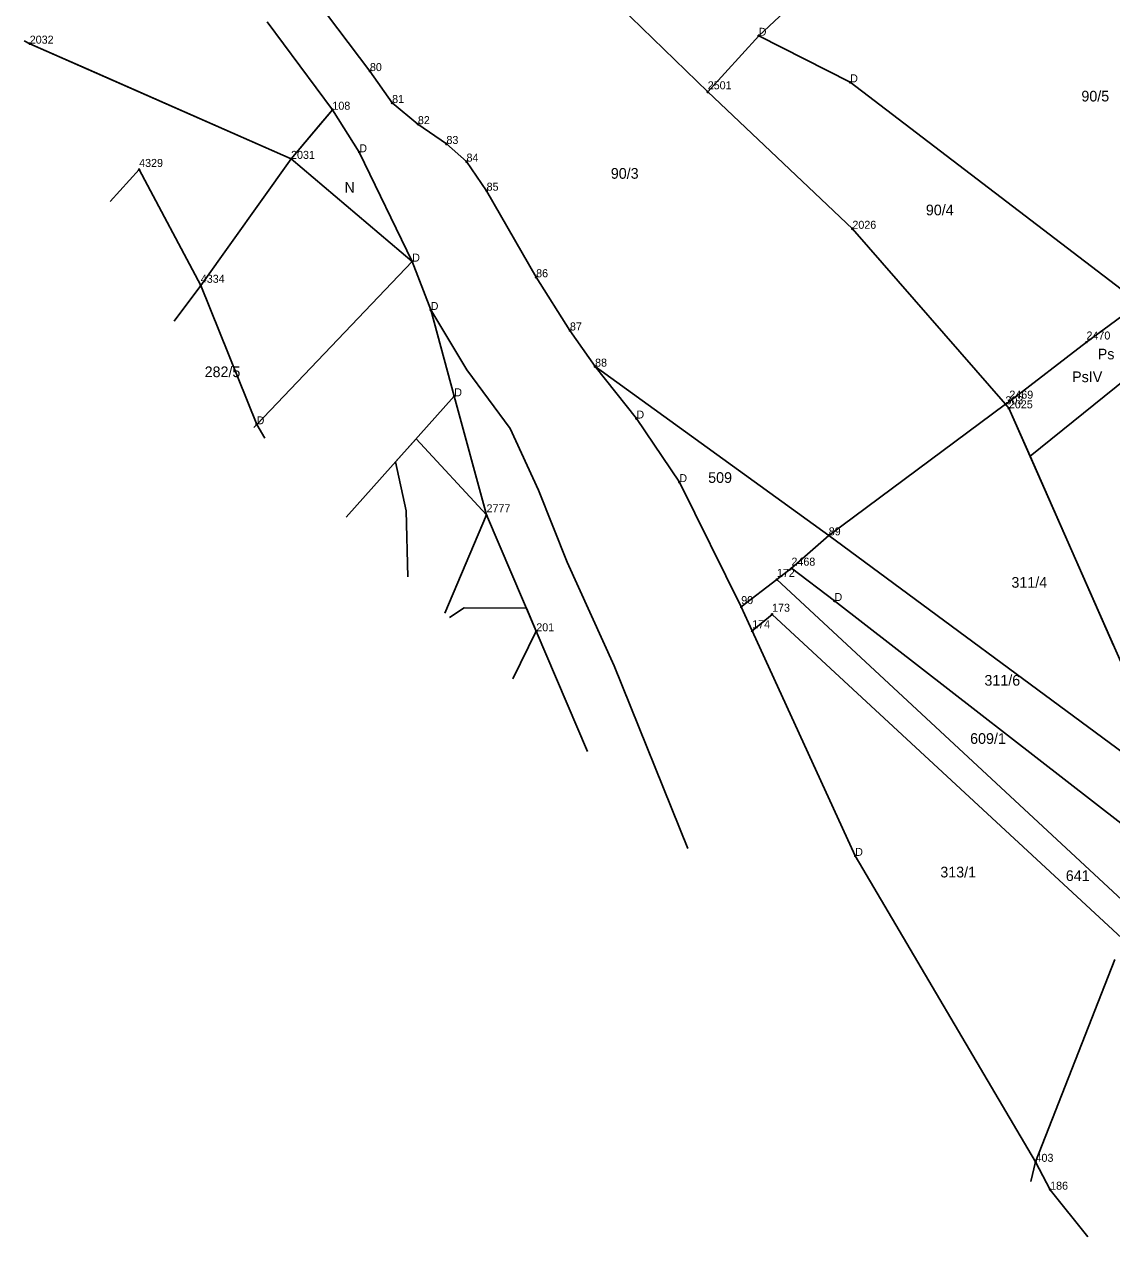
# Model space of a CAD drawing. Extents: x 7467189 to 7469366, y 5491487 to 5492734.
# Drawn here: x 7467502.5 to 7467655.3, y 5491844.1 to 5492014.5 of the extents above; entities that cross this region are included whole.
import ezdxf

# ---------------------------------------------------------------- set-up
doc = ezdxf.new("R2010")
doc.units = 0
for name, color, linetype in [('203-punkt graniczny', 7, 'Continuous'), ('203-punkt graniczny-Atr103', 7, 'Continuous'), ('209-oznaczenie konturu klasyfikacyjnego', 7, 'Continuous'), ('210-oznaczenie konturu użytku gruntowego', 7, 'Continuous'), ('211-numer działki ewidencyjnej', 7, 'Continuous'), ('217-kontur klasyfikacyjny', 7, 'Continuous'), ('218-kontur użytku gruntowego', 7, 'Continuous'), ('219-działka ewidencyjna', 7, 'Continuous')]:
    doc.layers.add(name, color=color, linetype=linetype)

# ---------------------------------------------------------------- blocks, each defined once
blk = doc.blocks.new('203')
blk.add_circle((0, 0), 0.09)

msp = doc.modelspace()

# ---------------------------------------------------------------- linework, layer by layer
at = {"layer": '217-kontur klasyfikacyjny'}
for points in [[(7467581.56, 5492021.52), (7467598.57, 5492004.96)], [(7467503.32, 5492011.74), (7467502.55, 5492012.14)], [(7467511.25, 5492008.24), (7467503.32, 5492011.74)], [(7467540.03, 5491995.55), (7467511.25, 5492008.24)], [(7467598.57, 5492004.96), (7467618.89, 5491985.73)], [(7467527.35, 5491977.76), (7467540.03, 5491995.55)], [(7467514.64, 5491989.54), (7467518.69, 5491994.05)], [(7467518.69, 5491994.05), (7467527.35, 5491977.76)], [(7467618.89, 5491985.73), (7467640.39, 5491961.07)], [(7467535.2, 5491958.25), (7467527.35, 5491977.76)], [(7467659.21, 5491975.28), (7467651.78, 5491969.8)], [(7467643.85, 5491953.77), (7467666.33, 5491971.9)], [(7467651.78, 5491969.8), (7467640.94, 5491961.48)], [(7467640.94, 5491961.48), (7467640.39, 5491961.07)], [(7467640.39, 5491961.07), (7467640.88, 5491960.5)], [(7467640.88, 5491960.5), (7467643.85, 5491953.77)], [(7467536.33, 5491956.3), (7467535.2, 5491958.25)], [(7467643.85, 5491953.77), (7467655.58, 5491927.15)], [(7467564.33, 5491932.48), (7467562.29, 5491931.11)], [(7467573.09, 5491932.44), (7467564.33, 5491932.48)], [(7467574.48, 5491929.17), (7467573.09, 5491932.44)], [(7467581.67, 5491912.3), (7467574.48, 5491929.17)], [(7467655.78, 5491883.07), (7467644.62, 5491854.62)], [(7467644.62, 5491854.62), (7467646.67, 5491850.7)], [(7467646.67, 5491850.7), (7467651.97, 5491844.09)]]:
    msp.add_lwpolyline(points, dxfattribs=at)
at = {"layer": '218-kontur użytku gruntowego'}
for points in [[(7467581.56, 5492021.52), (7467598.57, 5492004.96)], [(7467503.32, 5492011.74), (7467502.55, 5492012.14)], [(7467511.25, 5492008.24), (7467503.32, 5492011.74)], [(7467540.03, 5491995.55), (7467511.25, 5492008.24)], [(7467598.57, 5492004.96), (7467618.89, 5491985.73)], [(7467545.84, 5492002.46), (7467544.2, 5492000.51)], [(7467549.62, 5491996.48), (7467545.84, 5492002.46)], [(7467544.2, 5492000.51), (7467540.03, 5491995.55)], [(7467557.05, 5491981.12), (7467549.62, 5491996.48)], [(7467527.35, 5491977.76), (7467540.03, 5491995.55)], [(7467540.03, 5491995.55), (7467557.05, 5491981.12)], [(7467514.64, 5491989.54), (7467518.69, 5491994.05)], [(7467518.69, 5491994.05), (7467527.35, 5491977.76)], [(7467618.89, 5491985.73), (7467640.39, 5491961.07)], [(7467559.65, 5491974.32), (7467557.05, 5491981.12)], [(7467535.2, 5491958.25), (7467527.35, 5491977.76)], [(7467562.96, 5491962.19), (7467559.65, 5491974.32)], [(7467564.73, 5491965.9), (7467559.65, 5491974.32)], [(7467659.21, 5491975.28), (7467651.78, 5491969.8)], [(7467643.85, 5491953.77), (7467666.33, 5491971.9)], [(7467651.78, 5491969.8), (7467640.94, 5491961.48)], [(7467570.8, 5491957.67), (7467564.73, 5491965.9)], [(7467567.49, 5491945.51), (7467562.96, 5491962.19)], [(7467640.94, 5491961.48), (7467640.39, 5491961.07)], [(7467640.39, 5491961.07), (7467640.88, 5491960.5)], [(7467640.88, 5491960.5), (7467643.85, 5491953.77)], [(7467536.33, 5491956.3), (7467535.2, 5491958.25)], [(7467574.81, 5491948.99), (7467570.8, 5491957.67)], [(7467554.71, 5491952.96), (7467557.6, 5491956.19)], [(7467557.6, 5491956.19), (7467567.49, 5491945.51)], [(7467643.85, 5491953.77), (7467655.58, 5491927.15)], [(7467556.19, 5491946.09), (7467554.71, 5491952.96)], [(7467578.83, 5491938.89), (7467574.81, 5491948.99)], [(7467556.42, 5491936.81), (7467556.19, 5491946.09)], [(7467585.41, 5491924.33), (7467578.83, 5491938.89)], [(7467603.27, 5491932.61), (7467608.28, 5491936.44)], [(7467608.28, 5491936.44), (7467658.12, 5491890.18)], [(7467564.33, 5491932.48), (7467562.29, 5491931.11)], [(7467573.09, 5491932.44), (7467564.33, 5491932.48)], [(7467574.48, 5491929.17), (7467573.09, 5491932.44)], [(7467604.82, 5491929.22), (7467603.27, 5491932.61)], [(7467607.61, 5491931.54), (7467604.82, 5491929.22)], [(7467656.76, 5491886.05), (7467607.61, 5491931.54)], [(7467581.67, 5491912.3), (7467574.48, 5491929.17)], [(7467595.76, 5491898.63), (7467585.41, 5491924.33)], [(7467655.78, 5491883.07), (7467644.62, 5491854.62)], [(7467644.62, 5491854.62), (7467643.96, 5491851.86)], [(7467646.67, 5491850.7), (7467644.62, 5491854.62)], [(7467651.97, 5491844.09), (7467646.67, 5491850.7)]]:
    msp.add_lwpolyline(points, dxfattribs=at)
at = {"layer": '219-działka ewidencyjna'}
for points in [[(7467605.73, 5492012.85), (7467635.43, 5492040.66)], [(7467581.56, 5492021.52), (7467598.57, 5492004.96)], [(7467543.56, 5492017.84), (7467551.11, 5492007.89)], [(7467536.67, 5492014.81), (7467545.84, 5492002.46)], [(7467502.55, 5492012.14), (7467503.32, 5492011.74)], [(7467503.32, 5492011.74), (7467540.03, 5491995.55)], [(7467605.73, 5492012.85), (7467598.57, 5492004.96)], [(7467605.73, 5492012.85), (7467618.58, 5492006.31)], [(7467551.11, 5492007.89), (7467554.23, 5492003.41)], [(7467618.58, 5492006.31), (7467659.21, 5491975.28)], [(7467618.89, 5491985.73), (7467598.57, 5492004.96)], [(7467554.23, 5492003.41), (7467557.85, 5492000.43)], [(7467540.03, 5491995.55), (7467545.84, 5492002.46)], [(7467545.84, 5492002.46), (7467549.62, 5491996.48)], [(7467557.85, 5492000.43), (7467561.86, 5491997.65)], [(7467549.62, 5491996.48), (7467557.05, 5491981.12)], [(7467561.86, 5491997.65), (7467564.68, 5491995.17)], [(7467540.03, 5491995.55), (7467527.35, 5491977.76)], [(7467564.68, 5491995.17), (7467567.5, 5491991.08)], [(7467514.64, 5491989.54), (7467518.69, 5491994.05)], [(7467518.69, 5491994.05), (7467527.35, 5491977.76)], [(7467567.5, 5491991.08), (7467574.46, 5491978.92)], [(7467618.89, 5491985.73), (7467640.39, 5491961.07)], [(7467535.2, 5491958.25), (7467557.05, 5491981.12)], [(7467557.05, 5491981.12), (7467559.65, 5491974.32)], [(7467523.62, 5491972.74), (7467527.35, 5491977.76)], [(7467574.46, 5491978.92), (7467579.21, 5491971.44)], [(7467559.65, 5491974.32), (7467562.96, 5491962.19)], [(7467659.21, 5491975.28), (7467651.78, 5491969.8)], [(7467579.21, 5491971.44), (7467582.74, 5491966.36)], [(7467640.94, 5491961.48), (7467651.78, 5491969.8)], [(7467582.74, 5491966.36), (7467588.55, 5491959.07)], [(7467582.74, 5491966.36), (7467615.57, 5491942.65)], [(7467547.77, 5491945.2), (7467562.96, 5491962.19)], [(7467562.96, 5491962.19), (7467567.49, 5491945.51)], [(7467615.57, 5491942.65), (7467640.39, 5491961.07)], [(7467640.39, 5491961.07), (7467640.94, 5491961.48)], [(7467640.39, 5491961.07), (7467640.88, 5491960.5)], [(7467640.88, 5491960.5), (7467658.36, 5491920.84)], [(7467588.55, 5491959.07), (7467594.58, 5491950.13)], [(7467534.78, 5491957.81), (7467535.2, 5491958.25)], [(7467594.58, 5491950.13), (7467603.27, 5491932.61)], [(7467561.65, 5491931.73), (7467567.49, 5491945.51)], [(7467574.48, 5491929.17), (7467567.49, 5491945.51)], [(7467615.57, 5491942.65), (7467610.33, 5491938.02)], [(7467615.57, 5491942.65), (7467659.1, 5491910.5)], [(7467603.27, 5491932.61), (7467608.28, 5491936.44)], [(7467608.28, 5491936.44), (7467610.33, 5491938.02)], [(7467608.28, 5491936.44), (7467658.12, 5491890.18)], [(7467616.38, 5491933.43), (7467610.33, 5491938.02)], [(7467616.38, 5491933.43), (7467660.98, 5491898.77)], [(7467603.27, 5491932.61), (7467604.82, 5491929.22)], [(7467604.82, 5491929.22), (7467607.61, 5491931.54)], [(7467607.61, 5491931.54), (7467656.76, 5491886.05)], [(7467571.18, 5491922.49), (7467574.48, 5491929.17)], [(7467574.48, 5491929.17), (7467581.67, 5491912.3)], [(7467619.28, 5491897.61), (7467604.82, 5491929.22)], [(7467619.28, 5491897.61), (7467644.62, 5491854.62)], [(7467644.62, 5491854.62), (7467655.78, 5491883.07)], [(7467644.62, 5491854.62), (7467646.67, 5491850.7)], [(7467646.67, 5491850.7), (7467651.97, 5491844.09)]]:
    msp.add_lwpolyline(points, dxfattribs=at)

# ---------------------------------------------------------------- block references
at = {"layer": '203-punkt graniczny'}
for p in [(7467503.32, 5492011.74), (7467605.73, 5492012.85), (7467551.11, 5492007.89), (7467618.58, 5492006.31), (7467598.57, 5492004.96), (7467554.23, 5492003.41), (7467545.84, 5492002.46), (7467557.85, 5492000.43), (7467549.62, 5491996.48), (7467561.86, 5491997.65), (7467540.03, 5491995.55), (7467564.68, 5491995.17), (7467518.69, 5491994.05), (7467567.5, 5491991.08), (7467618.89, 5491985.73), (7467557.05, 5491981.12), (7467527.35, 5491977.76), (7467574.46, 5491978.92), (7467559.65, 5491974.32), (7467579.21, 5491971.44), (7467651.78, 5491969.8), (7467582.74, 5491966.36), (7467562.96, 5491962.19), (7467640.39, 5491961.07), (7467640.88, 5491960.5), (7467640.94, 5491961.48), (7467588.55, 5491959.07), (7467535.2, 5491958.25), (7467594.58, 5491950.13), (7467567.49, 5491945.51), (7467615.57, 5491942.65), (7467608.28, 5491936.44), (7467610.33, 5491938.02), (7467616.38, 5491933.43), (7467603.27, 5491932.61), (7467607.61, 5491931.54), (7467574.48, 5491929.17), (7467604.82, 5491929.22), (7467619.28, 5491897.61), (7467644.62, 5491854.62), (7467646.67, 5491850.7)]:
    msp.add_blockref('203', p, dxfattribs=at)

# ---------------------------------------------------------------- texts
at = {"layer": '203-punkt graniczny-Atr103'}
for s, height, p in [('D', 1.12, (7467605.73, 5492012.85)), ('2032', 1.125, (7467503.32, 5492011.74)), ('80', 1.125, (7467551.11, 5492007.89)), ('2501', 1.125, (7467598.57, 5492005.33)), ('D', 1.12, (7467618.58, 5492006.31)), ('108', 1.125, (7467545.84, 5492002.46)), ('81', 1.125, (7467554.23, 5492003.41)), ('82', 1.125, (7467557.85, 5492000.43)), ('83', 1.125, (7467561.86, 5491997.65)), ('2031', 1.125, (7467540.03, 5491995.55)), ('D', 1.12, (7467549.62, 5491996.48)), ('84', 1.125, (7467564.68, 5491995.17)), ('4329', 1.125, (7467518.69, 5491994.42)), ('85', 1.125, (7467567.5, 5491991.08)), ('2026', 1.125, (7467618.89, 5491985.73)), ('D', 1.12, (7467557.05, 5491981.12)), ('4334', 1.125, (7467527.35, 5491978.14)), ('86', 1.125, (7467574.46, 5491978.92)), ('D', 1.12, (7467559.65, 5491974.32)), ('87', 1.125, (7467579.21, 5491971.44)), ('2470', 1.125, (7467651.78, 5491970.17)), ('88', 1.125, (7467582.74, 5491966.36)), ('D', 1.12, (7467562.96, 5491962.19)), ('303', 1.125, (7467640.39, 5491961.07)), ('2469', 1.125, (7467640.94, 5491961.86)), ('2025', 1.125, (7467640.88, 5491960.5)), ('D', 1.12, (7467535.2, 5491958.25)), ('D', 1.12, (7467588.55, 5491959.07)), ('D', 1.12, (7467594.58, 5491950.13)), ('2777', 1.125, (7467567.49, 5491945.89)), ('89', 1.125, (7467615.57, 5491942.65)), ('2468', 1.125, (7467610.33, 5491938.39)), ('172', 1.125, (7467608.28, 5491936.82)), ('90', 1.125, (7467603.27, 5491932.99)), ('173', 1.125, (7467607.61, 5491931.92)), ('D', 1.12, (7467616.38, 5491933.43)), ('201', 1.125, (7467574.48, 5491929.17)), ('174', 1.125, (7467604.82, 5491929.6)), ('D', 1.12, (7467619.28, 5491897.61)), ('403', 1.125, (7467644.62, 5491854.62)), ('186', 1.125, (7467646.67, 5491850.7))]:
    msp.add_text(s, height=height, dxfattribs=at).set_placement(p)
at = {"layer": '209-oznaczenie konturu klasyfikacyjnego'}
msp.add_text('PsIV', height=1.5, dxfattribs=at).set_placement((7467649.76, 5491964.18))
at = {"layer": '210-oznaczenie konturu użytku gruntowego'}
for s, p in [('N', (7467547.54, 5491990.79)), ('Ps', (7467653.36, 5491967.38))]:
    msp.add_text(s, height=1.5, dxfattribs=at).set_placement(p)
at = {"layer": '211-numer działki ewidencyjnej'}
for s, p in [('90/5', (7467651.06, 5492003.62)), ('90/3', (7467584.95, 5491992.76)), ('90/4', (7467629.21, 5491987.62)), ('282/5', (7467527.89, 5491964.88)), ('509', (7467598.63, 5491950.02)), ('311/4', (7467641.23, 5491935.29)), ('311/6', (7467637.44, 5491921.53)), ('609/1', (7467635.43, 5491913.35)), ('313/1', (7467631.24, 5491894.58)), ('641', (7467648.87, 5491894.08))]:
    msp.add_text(s, height=1.5, dxfattribs=at).set_placement(p)

doc.saveas('drawing.dxf')
